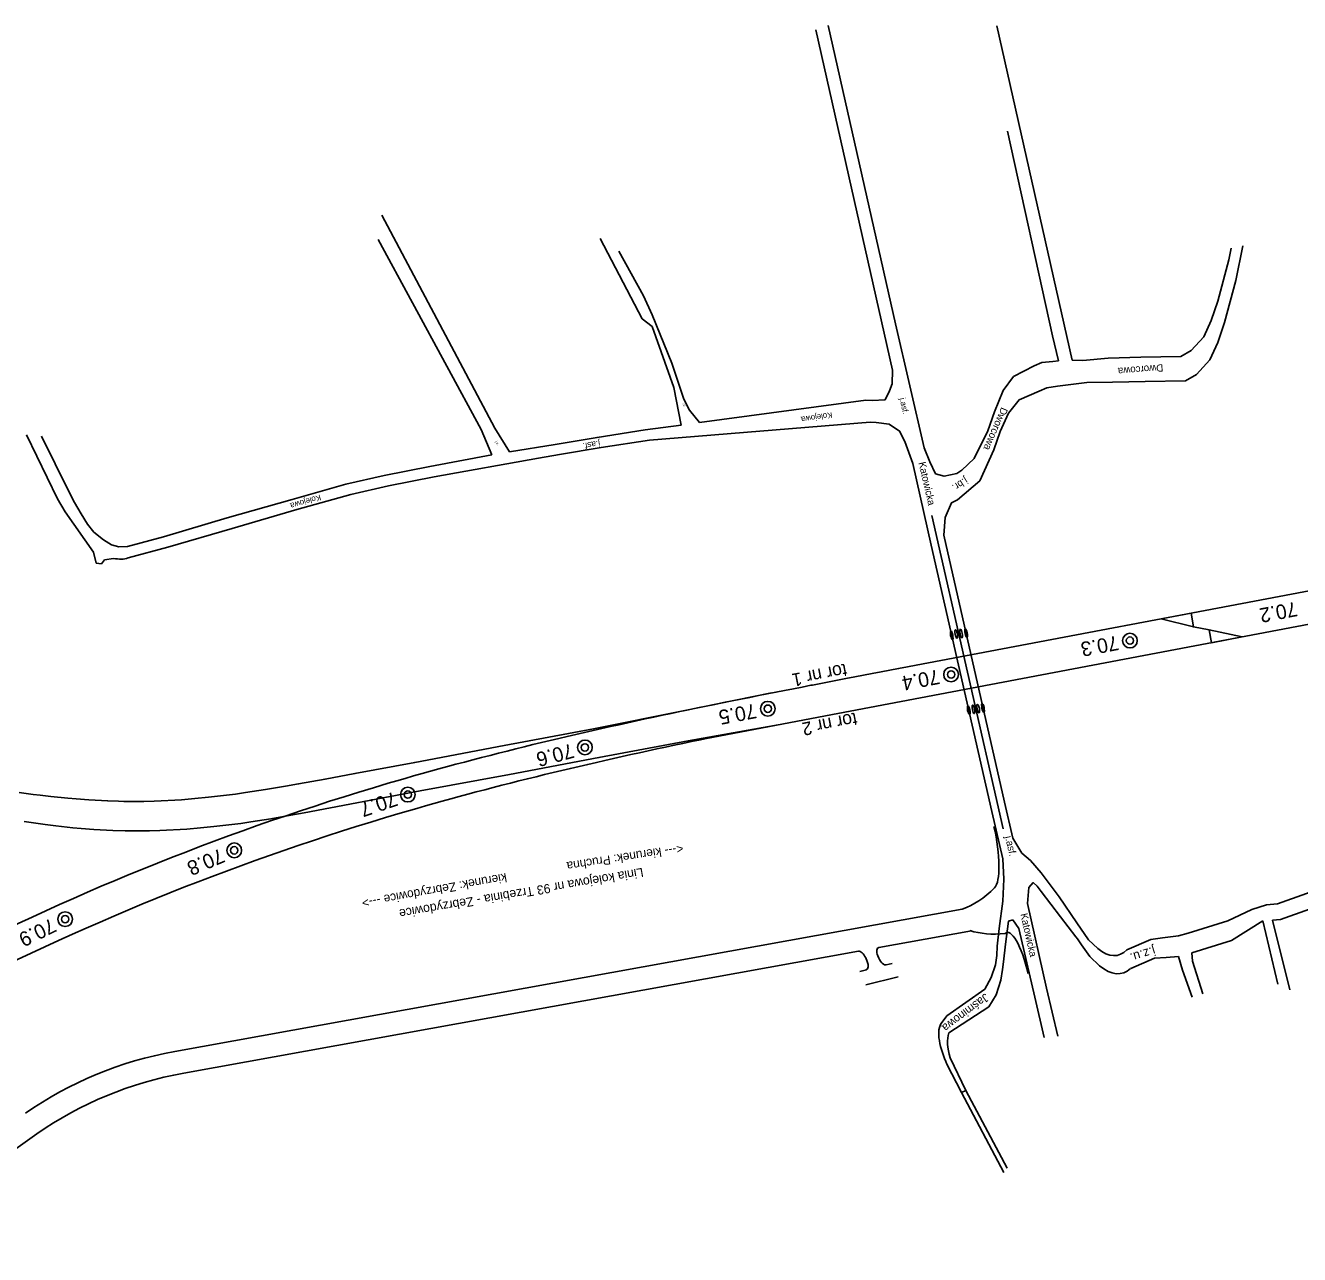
# Model space of a CAD drawing. Extents: x 6541740 to 6556805, y 5525233 to 5530361.
# Drawn here: x 6554888.2 to 6555063.1, y 5525670.1 to 5525838.8 of the extents above; entities that cross this region are included whole.
import ezdxf

# ---------------------------------------------------------------- set-up
doc = ezdxf.new("R2010")
doc.units = 0
for name, color, linetype in [('Default', 7, 'Continuous'), ('TOR_PS_OPIS_T-numeracja torow i rozjazdow', 7, 'Continuous'), ('TOR_SCH-budynki', 7, 'Continuous'), ('TOR_SCH-hektometry', 7, 'Continuous'), ('TOR_SCH-obiekty projektowane', 7, 'Continuous'), ('TOR_SCH-opisy glowne', 7, 'Continuous'), ('TOR_SCH-przejazdy+drogi istniejace', 7, 'Continuous'), ('TOR_SCH-przejazdy+drogi projektowane', 7, 'Continuous'), ('TOR_SCH-tory i rozjazdy do rozbiorki', 7, 'Continuous'), ('TOR_SCH-tory projektowane', 7, 'Continuous')]:
    doc.layers.add(name, color=color, linetype=linetype)

# ---------------------------------------------------------------- blocks, each defined once
blk = doc.blocks.new('4010_1')
at = {"layer": 'Default'}
for radius in [0.75, 0.375]:
    blk.add_circle((0, 0), radius, dxfattribs=at)

msp = doc.modelspace()

# ---------------------------------------------------------------- linework, layer by layer
at = {"layer": 'TOR_SCH-budynki'}
for centre in [(6555017.34, 5525755.36), (6555015.36, 5525755.06), (6555015.99, 5525755.25), (6555016.66, 5525755.31), (6555018.35, 5525744.91), (6555019.01, 5525745.02), (6555019.66, 5525745.11), (6555017.7, 5525744.79)]:
    msp.add_ellipse(centre, major_axis=(-0.112, 0.59), ratio=0.25, dxfattribs=at)
at = {"layer": 'TOR_SCH-obiekty projektowane'}
msp.add_line((6555012.65, 5525771.52), (6555022.43, 5525728.5), dxfattribs=at)
at = {"layer": 'TOR_SCH-przejazdy+drogi istniejace'}
for p, q in [((6554996.7, 5525838.18), (6555007.24, 5525791.47)), ((6554998.39, 5525838.77), (6555007.63, 5525797.82)), ((6555031.89, 5525792.83), (6555021.54, 5525838.72)), ((6555023.04, 5525824.27), (6555029.2, 5525796.17)), ((6554937.08, 5525812.72), (6554952.6, 5525783.49)), ((6554950.72, 5525783.34), (6554936.61, 5525809.38)), ((6554972.87, 5525798.51), (6554967.1, 5525809.53)), ((6554969.64, 5525807.78), (6554973.04, 5525801.66)), ((6554973.04, 5525801.66), (6554974.24, 5525799.08)), ((6554974.24, 5525797.45), (6554972.87, 5525798.51)), ((6554974.24, 5525799.08), (6554976.94, 5525792.43)), ((6554977.2, 5525789.1), (6554974.24, 5525797.45)), ((6555007.63, 5525797.82), (6555011.56, 5525780.78)), ((6555029.2, 5525796.17), (6555030.01, 5525792.73)), ((6554976.94, 5525792.43), (6554978.58, 5525787.48)), ((6555007.24, 5525791.47), (6555007.18, 5525789.58)), ((6554978.19, 5525783.92), (6554977.2, 5525789.1)), ((6554978.58, 5525787.48), (6554979.35, 5525785.97)), ((6554979.35, 5525785.97), (6554980.71, 5525784.26)), ((6554892.54, 5525773.8), (6554888.3, 5525782.58)), ((6554890.38, 5525782.42), (6554894.13, 5525774.8)), ((6554952.22, 5525779.82), (6554950.72, 5525783.34)), ((6554952.6, 5525783.49), (6554954.62, 5525780.24)), ((6554943.71, 5525778.23), (6554952.22, 5525779.82)), ((6554958.63, 5525779.36), (6554944.28, 5525776.84)), ((6554932.17, 5525775.8), (6554937.42, 5525777.02)), ((6554937.42, 5525777.02), (6554943.71, 5525778.23)), ((6554924.8, 5525773.73), (6554932.17, 5525775.8)), ((6554938.02, 5525775.58), (6554932.84, 5525774.41)), ((6554944.28, 5525776.84), (6554938.02, 5525775.58)), ((6554893.62, 5525772.01), (6554892.54, 5525773.8)), ((6554894.13, 5525774.8), (6554894.87, 5525773.31)), ((6554915.86, 5525771.17), (6554924.8, 5525773.73)), ((6554932.84, 5525774.41), (6554925.44, 5525772.33)), ((6554897.48, 5525766.47), (6554893.62, 5525772.01)), ((6554894.87, 5525773.31), (6554895.79, 5525771.72)), ((6554895.79, 5525771.72), (6554896.68, 5525770.33)), ((6554925.44, 5525772.33), (6554916.54, 5525769.72)), ((6554896.68, 5525770.33), (6554897.57, 5525769.23)), ((6554907.1, 5525768.57), (6554915.86, 5525771.17)), ((6554897.57, 5525769.23), (6554898.88, 5525768.16)), ((6554902.16, 5525767.28), (6554907.1, 5525768.57)), ((6554916.54, 5525769.72), (6554907.71, 5525767.15)), ((6554897.89, 5525764.95), (6554897.48, 5525766.47)), ((6554898.88, 5525768.16), (6554899.99, 5525767.48)), ((6554899.99, 5525767.48), (6554900.96, 5525767.21)), ((6554900.96, 5525767.21), (6554902.16, 5525767.28)), ((6554907.71, 5525767.15), (6554902.26, 5525765.69)), ((6554898.59, 5525764.87), (6554897.89, 5525764.95)), ((6554899.02, 5525765.43), (6554898.59, 5525764.87)), ((6554900.26, 5525765.63), (6554899.02, 5525765.43)), ((6555024.98, 5525725.17), (6555023.74, 5525727.23)), ((6555022.38, 5525724.37), (6555022.53, 5525721.57)), ((6555025.95, 5525720.43), (6555026.55, 5525721.13)), ((6555025.95, 5525720.43), (6555025.76, 5525718.25)), ((6555058.6, 5525718.09), (6555056.57, 5525717.41)), ((6555024.6, 5525714.83), (6555023.78, 5525716.02)), ((6555060.15, 5525707.17), (6555058.07, 5525715.88)), ((6555059.4, 5525715.97), (6555061.79, 5525706.4)), ((6555014.68, 5525702.81), (6555014.04, 5525701.95)), ((6555017.32, 5525692.57), (6555015.17, 5525697.06)), ((6555014.71, 5525696.19), (6555016.7, 5525692.31)), ((6555016.7, 5525692.31), (6555017.32, 5525692.57)), ((6555016.7, 5525692.31), (6555022.54, 5525681.34)), ((6555017.32, 5525692.57), (6555023, 5525681.9))]:
    msp.add_line(p, q, dxfattribs=at)
for points in [[(6555033.94, 5525789.75), (6555037.46, 5525789.81), (6555041.92, 5525789.92), (6555047.48, 5525790.02), (6555048.98, 5525790.89), (6555050.79, 5525792.86), (6555051.89, 5525795.24), (6555052.82, 5525797.99), (6555054.39, 5525803.78), (6555055.35, 5525808.53)], [(6555033.35, 5525792.77), (6555036.86, 5525793.13), (6555041.32, 5525793.24), (6555046.83, 5525793.34), (6555048.24, 5525794.16), (6555049.97, 5525796.03), (6555051, 5525798.26), (6555051.9, 5525800.92), (6555053.43, 5525806.6), (6555053.76, 5525808.21)], [(6555029.27, 5525792.66), (6555030.01, 5525792.73)], [(6555031.89, 5525792.83), (6555033.35, 5525792.77)], [(6555016.76, 5525777.72), (6555018.47, 5525779.35), (6555020.31, 5525783.15), (6555021.23, 5525785.72), (6555022.44, 5525788.69), (6555023.84, 5525790.58), (6555026.67, 5525792.05), (6555027.76, 5525792.52), (6555029.27, 5525792.66)], [(6555007.18, 5525789.58), (6555006.81, 5525788.62), (6555006.21, 5525787.37), (6555004.44, 5525787.3), (6555003.58, 5525787.33)], [(6555016.15, 5525773.67), (6555019.21, 5525776.25), (6555021.13, 5525780.53), (6555022.03, 5525783.04), (6555023.17, 5525785.57), (6555024.61, 5525787.37), (6555027.39, 5525788.6), (6555028.44, 5525789.05), (6555029.91, 5525789.25)], [(6555029.91, 5525789.25), (6555032.1, 5525789.55), (6555033.94, 5525789.75)], [(6555003.58, 5525787.33), (6554980.71, 5525784.26)], [(6555004.15, 5525784.32), (6554973.84, 5525781.86), (6554967.23, 5525780.85), (6554961.5, 5525779.87), (6554958.63, 5525779.36)], [(6555010.03, 5525778.66), (6555008.93, 5525781.68), (6555008.2, 5525783.1), (6555006.77, 5525784.05), (6555004.98, 5525784.27), (6555004.15, 5525784.32)], [(6554978.19, 5525783.92), (6554973.27, 5525783.26), (6554966.65, 5525782.24), (6554960.92, 5525781.27), (6554954.62, 5525780.24)], [(6555011.56, 5525780.78), (6555012.38, 5525778.87), (6555013.15, 5525777.24), (6555014.32, 5525776.92), (6555016.06, 5525777.28), (6555016.76, 5525777.72)], [(6555022.38, 5525724.37), (6555020.86, 5525730.87), (6555012.53, 5525767.45), (6555010.03, 5525778.66)], [(6555014.3, 5525768.83), (6555014.48, 5525771.26), (6555015.34, 5525773.27), (6555016.15, 5525773.67)], [(6555014.3, 5525768.83), (6555022.63, 5525732.15), (6555023.74, 5525727.23)], [(6555098.57, 5525731.15), (6555095, 5525730.9), (6555087.57, 5525727.52), (6555083.16, 5525725.42), (6555081.62, 5525725.24), (6555078.11, 5525724.01), (6555071.95, 5525722.81), (6555068.4, 5525721.36), (6555067.65, 5525721.06), (6555064.08, 5525719.61), (6555060.11, 5525718.2), (6555058.6, 5525718.09)], [(6555099.7, 5525728.48), (6555095.6, 5525728.43), (6555088.01, 5525725.37), (6555083.59, 5525723.27), (6555082.03, 5525723.09), (6555078.53, 5525721.86), (6555072.37, 5525720.65), (6555068.08, 5525718.91), (6555064.51, 5525717.46), (6555060.52, 5525716.05), (6555059.4, 5525715.97), (6555059.4, 5525715.97), (6555059.4, 5525715.97)], [(6555024.98, 5525725.17), (6555026.17, 5525724.17), (6555027.63, 5525722.47), (6555030.13, 5525719.15), (6555030.13, 5525719.15)], [(6555022.53, 5525721.57), (6555022.39, 5525718.58), (6555021.88, 5525714.8), (6555021.61, 5525712.39), (6555021.54, 5525711.11)], [(6555026.55, 5525721.13), (6555026.55, 5525721.13), (6555027.09, 5525720.62), (6555027.63, 5525719.9), (6555030.3, 5525716.4)], [(6555025.76, 5525718.25), (6555028.38, 5525706.65), (6555029.93, 5525700.03)], [(6555030.13, 5525719.15), (6555032.53, 5525715.61), (6555034.15, 5525713.28), (6555035.42, 5525712.06)], [(6555023.78, 5525716.02), (6555023.16, 5525715.82), (6555022.74, 5525712.65), (6555022.47, 5525710.24), (6555022.33, 5525709.21)], [(6555030.3, 5525716.4), (6555032.43, 5525713.67), (6555032.63, 5525713.41), (6555033.21, 5525712.58), (6555034.33, 5525710.98), (6555035.65, 5525709.7)], [(6555046.51, 5525713.8), (6555047.82, 5525714.2), (6555053.27, 5525715.87), (6555056.57, 5525717.41)], [(6555048.34, 5525711.48), (6555053.81, 5525713.16), (6555058.07, 5525715.88)], [(6555028.07, 5525699.88), (6555026.79, 5525705.41), (6555024.6, 5525714.83)], [(6555039.42, 5525711.9), (6555042.73, 5525713.33), (6555044.29, 5525713.53)], [(6555044.29, 5525713.53), (6555046.51, 5525713.8)], [(6555021.54, 5525711.11), (6555021.39, 5525709.83), (6555020.8, 5525708.09), (6555019.89, 5525706.48), (6555014.68, 5525702.81)], [(6555039.94, 5525709.33), (6555043.23, 5525710.76), (6555044.8, 5525710.86)], [(6555044.8, 5525710.86), (6555046.53, 5525710.97)], [(6555048.37, 5525705.39), (6555047.06, 5525709.1), (6555046.53, 5525710.97)], [(6555048.34, 5525711.48), (6555048.45, 5525710.35), (6555049.84, 5525705.84)], [(6555022.33, 5525709.21), (6555022.13, 5525707.72), (6555021.46, 5525705.73), (6555020.46, 5525704.08), (6555014.99, 5525700.49)]]:
    msp.add_lwpolyline(points, dxfattribs=at)
for centre, major_axis, ratio, start_param, end_param in [((6554897.34, 5525776.23), (-5.33, 10.37), 0.5, 2.747069, 3.066585), ((6555031.73, 5525744.58), (6.34, -33.45), 0.250307, 5.994146, 6.456591), ((6555031.51, 5525746.2), (7.11, -37.55), 0.250277, 5.994158, 6.432263), ((6555016.44, 5525698.24), (-2.05, 3.99), 0.5, 0.19715, 1.026213), ((6555018.19, 5525696.71), (-2.43, 4.74), 0.5, 0.43659, 1.248227), ((6555018.47, 5525697.33), (-3.55, 6.9), 0.5, 1.020936, 1.481176)]:
    msp.add_ellipse(centre, major_axis=major_axis, ratio=ratio, start_param=start_param, end_param=end_param, dxfattribs=at)
at = {"layer": 'TOR_SCH-przejazdy+drogi projektowane'}
for p, q in [((6555016.82, 5525717.49), (6554908.65, 5525697.93)), ((6555018.07, 5525714.52), (6555005.35, 5525712.22)), ((6555002.55, 5525711.71), (6554909.9, 5525694.96)), ((6555003.56, 5525710.79), (6555003.77, 5525710.29)), ((6555005.21, 5525711.08), (6555005.35, 5525710.75)), ((6555002.76, 5525708.94), (6555003.64, 5525709.16)), ((6555006.37, 5525709.83), (6555007.19, 5525710.03)), ((6555003.56, 5525707.11), (6555008, 5525708.18)), ((6554889.74, 5525686.63), (6554873.22, 5525675.05))]:
    msp.add_line(p, q, dxfattribs=at)
for centre, major_axis, ratio, start_param, end_param in [((6555019.62, 5525727.36), (-1.35, 7.12), 0.25, 3.312433, 4.873816), ((6554988.19, 5525861.32), (-27.33, 144.18), 0.25, 3.178225, 3.312433), ((6555090.53, 5525849.22), (74.58, 133.88), 0.25, 3.195453, 3.311202), ((6555024.31, 5525707.15), (-1.35, 7.12), 0.25, 4.873816, 6.452794), ((6555005.78, 5525711.19), (0.51, -1), 0.5, 2.99045, 4.561247), ((6555002.98, 5525710.68), (-0.51, 1), 0.5, 4.561247, 6.132043), ((6555005.92, 5525710.85), (0.51, -1), 0.5, 4.561247, 6.164201), ((6555003.19, 5525710.18), (-0.51, 1), 0.5, 3.022608, 4.561247), ((6554986.22, 5525513.69), (-92.12, 179.35), 0.5, 6.132043, 6.351843), ((6554986.22, 5525513.69), (-90.64, 176.46), 0.5, 6.132043, 6.351843)]:
    msp.add_ellipse(centre, major_axis=major_axis, ratio=ratio, start_param=start_param, end_param=end_param, dxfattribs=at)
at = {"layer": 'TOR_SCH-tory i rozjazdy do rozbiorki'}
for points in [[(6555044.13, 5525757.34), (6555048.26, 5525758.12), (6555048.55, 5525756.22)], [(6555055.23, 5525754.85), (6555051.03, 5525754.05), (6555050.73, 5525755.8)]]:
    msp.add_lwpolyline(points, close=True, dxfattribs=at)
for points in [[(6555050.73, 5525755.8), (6555048.55, 5525756.22)], [(6554990.62, 5525747.15), (6554990.62, 5525747.15), (6554978.5, 5525744.69), (6554978.5, 5525744.69), (6554966.17, 5525742.23), (6554966.17, 5525742.23), (6554953.9, 5525739.93), (6554953.9, 5525739.93), (6554941.61, 5525737.63), (6554941.61, 5525737.63), (6554933.41, 5525736.08), (6554929.31, 5525735.32), (6554929.31, 5525735.32), (6554925.67, 5525734.66), (6554923.85, 5525734.34), (6554921.11, 5525733.89), (6554918.37, 5525733.47), (6554916.99, 5525733.28), (6554916.99, 5525733.28), (6554915.35, 5525733.06), (6554914.53, 5525732.97), (6554913.3, 5525732.83), (6554911.44, 5525732.65), (6554909.58, 5525732.5), (6554908.65, 5525732.43), (6554906.78, 5525732.34), (6554905.84, 5525732.3), (6554904.43, 5525732.27), (6554904.43, 5525732.27), (6554902.78, 5525732.26), (6554901.68, 5525732.27), (6554900.95, 5525732.29), (6554899.47, 5525732.34), (6554899.47, 5525732.34), (6554898.6, 5525732.37), (6554896.87, 5525732.48), (6554895.12, 5525732.61), (6554893.96, 5525732.71), (6554891.63, 5525732.94), (6554891.62, 5525732.94), (6554890.19, 5525733.11), (6554889.23, 5525733.23), (6554887.3, 5525733.49)], [(6554991.55, 5525742.77), (6554979.19, 5525740.59), (6554966.92, 5525738.28), (6554966.92, 5525738.28), (6554954.65, 5525735.97), (6554954.65, 5525735.97), (6554942.36, 5525733.7), (6554942.36, 5525733.7), (6554938.26, 5525732.93), (6554930.05, 5525731.38), (6554930.05, 5525731.38), (6554926.42, 5525730.7), (6554924.59, 5525730.37), (6554921.86, 5525729.89), (6554920.03, 5525729.59), (6554919.11, 5525729.45), (6554917.74, 5525729.25), (6554917.74, 5525729.25), (6554916.1, 5525729.04), (6554915.28, 5525728.94), (6554914.05, 5525728.8), (6554912.19, 5525728.62), (6554910.33, 5525728.46), (6554909.4, 5525728.4), (6554907.53, 5525728.3), (6554906.6, 5525728.26), (6554905.19, 5525728.22), (6554905.19, 5525728.22), (6554903.71, 5525728.21), (6554902.97, 5525728.21), (6554901.86, 5525728.22), (6554900.18, 5525728.27), (6554900.18, 5525728.27), (6554899.31, 5525728.31), (6554897.57, 5525728.41), (6554895.83, 5525728.54), (6554894.66, 5525728.65), (6554893.88, 5525728.73), (6554892.33, 5525728.91), (6554892.32, 5525728.91), (6554890.88, 5525729.09), (6554889.91, 5525729.22), (6554887.98, 5525729.5)]]:
    msp.add_lwpolyline(points, dxfattribs=at)
at = {"layer": 'TOR_SCH-tory projektowane'}
for p, q in [((6555221.45, 5525790.95), (6555010.48, 5525750.96)), ((6555222.13, 5525786.49), (6554997.05, 5525743.82)), ((6554997.05, 5525743.82), (6554981.45, 5525740.86))]:
    msp.add_line(p, q, dxfattribs=at)
for points in [[(6555010.48, 5525750.96), (6555009.27, 5525750.73), (6555008.07, 5525750.5), (6555006.86, 5525750.27), (6555005.66, 5525750.04), (6555004.45, 5525749.82), (6555003.25, 5525749.59), (6555002.05, 5525749.36), (6555000.84, 5525749.13), (6554996.23, 5525748.24)], [(6554996.23, 5525748.24), (6554996.03, 5525748.2), (6554994.83, 5525747.97), (6554993.62, 5525747.73), (6554992.42, 5525747.5), (6554991.22, 5525747.26), (6554990.02, 5525747.03), (6554988.82, 5525746.79), (6554987.62, 5525746.55), (6554986.42, 5525746.31), (6554985.22, 5525746.07), (6554984.02, 5525745.83), (6554982.82, 5525745.58), (6554981.63, 5525745.34), (6554980.43, 5525745.09), (6554979.23, 5525744.85), (6554978.04, 5525744.6), (6554976.84, 5525744.34), (6554975.65, 5525744.09), (6554974.46, 5525743.84), (6554973.26, 5525743.58), (6554972.07, 5525743.32), (6554970.88, 5525743.06), (6554969.69, 5525742.8), (6554968.5, 5525742.54), (6554967.31, 5525742.27), (6554966.13, 5525742), (6554964.94, 5525741.73), (6554963.75, 5525741.46), (6554962.57, 5525741.18), (6554961.39, 5525740.9), (6554960.2, 5525740.62), (6554959.02, 5525740.34), (6554957.84, 5525740.06), (6554956.66, 5525739.77), (6554955.49, 5525739.48), (6554954.31, 5525739.18), (6554953.14, 5525738.89), (6554951.96, 5525738.59), (6554950.79, 5525738.29), (6554949.62, 5525737.98), (6554948.45, 5525737.67), (6554947.28, 5525737.36), (6554946.11, 5525737.05), (6554944.95, 5525736.73), (6554943.78, 5525736.41), (6554942.62, 5525736.09), (6554941.46, 5525735.76), (6554940.3, 5525735.43), (6554939.14, 5525735.09), (6554937.99, 5525734.75)], [(6554981.45, 5525740.86), (6554980.85, 5525740.74), (6554979.65, 5525740.49), (6554978.46, 5525740.23), (6554977.27, 5525739.98), (6554976.07, 5525739.73), (6554974.88, 5525739.47), (6554973.69, 5525739.21), (6554972.5, 5525738.95), (6554971.31, 5525738.69), (6554970.12, 5525738.43), (6554968.93, 5525738.16), (6554967.74, 5525737.89), (6554966.56, 5525737.62), (6554965.37, 5525737.35), (6554964.19, 5525737.07), (6554963, 5525736.79), (6554961.82, 5525736.51), (6554960.64, 5525736.23), (6554959.46, 5525735.95), (6554958.28, 5525735.66), (6554957.1, 5525735.37), (6554955.93, 5525735.07), (6554954.75, 5525734.78), (6554953.58, 5525734.48), (6554952.41, 5525734.18), (6554951.24, 5525733.87), (6554950.07, 5525733.56), (6554948.9, 5525733.25), (6554947.73, 5525732.94), (6554946.57, 5525732.62), (6554945.4, 5525732.3), (6554944.24, 5525731.97), (6554943.08, 5525731.64), (6554941.92, 5525731.31), (6554940.76, 5525730.98), (6554939.6, 5525730.64)]]:
    msp.add_lwpolyline(points, dxfattribs=at)
for centre, major_axis, start_param, end_param in [((6555516.78, 5524462.45), (-640.8, 1247.55), 6.188263, 6.378108), ((6555517.43, 5524460.63), (-639.66, 1245.32), 6.188355, 6.378016)]:
    msp.add_ellipse(centre, major_axis=major_axis, ratio=0.5, start_param=start_param, end_param=end_param, dxfattribs=at)

# ---------------------------------------------------------------- block references
at = {"layer": 'TOR_SCH-hektometry', "xscale": 1.345963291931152, "yscale": 1.345963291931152}
for p in [(6555039.84, 5525754.34), (6555015.28, 5525749.69), (6554990.11, 5525744.99)]:
    msp.add_blockref('4010_1', p, dxfattribs=at)
at = {"layer": 'TOR_SCH-hektometry'}
for p, xscale, yscale, rotation in [((6554964.99, 5525739.68), 1.345963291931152, 1.3459632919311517, 4.247698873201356), ((6554940.67, 5525733.2), 1.345963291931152, 1.3459632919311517, 4.247698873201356), ((6554916.83, 5525725.55), 1.345963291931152, 1.3459632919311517, 4.247698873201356), ((6554893.61, 5525716.1), 1.3459632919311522, 1.3459632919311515, 7.546628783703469)]:
    msp.add_blockref('4010_1', p, dxfattribs=dict(at, xscale=xscale, yscale=yscale, rotation=rotation))

# ---------------------------------------------------------------- texts
at = {"layer": 'TOR_PS_OPIS_T-numeracja torow i rozjazdow'}
for s, rotation, p in [('tor nr 1', 191.0237, (6555000.79, 5525751.21)), ('tor nr 2', 191.0133, (6555002.18, 5525744.49))]:
    msp.add_text(s, height=1.8, rotation=rotation, dxfattribs=at).set_placement(p)
at = {"layer": 'TOR_SCH-hektometry'}
for s, rotation, p in [('70.2', 190.7691, (6555062.62, 5525759.7)), ('70.3', 190.7691, (6555038.07, 5525755.05)), ('70.4', 190.7691, (6555013.5, 5525750.39)), ('70.5', 190.7691, (6554988.34, 5525745.7)), ('70.6', 195.0168, (6554963.17, 5525740.25)), ('70.7', 198.8052, (6554938.82, 5525733.65)), ('70.8', 202.8689, (6554914.95, 5525725.87)), ('70.9', 206.1678, (6554891.71, 5525716.31))]:
    msp.add_text(s, height=2, rotation=rotation, dxfattribs=at).set_placement(p)
at = {"layer": 'TOR_SCH-opisy glowne'}
for s, height, rotation, p in [('<--- kierunek: Pruchna', 1.2202, 188.7861, (6554978.41, 5525726.41)), ('Linia kolejowa nr 93 Trzebinia - Zebrzydowice', 1.2535, 189.7097, (6554972.91, 5525723.16)), ('kierunek: Zebrzydowice --->', 1.2202, 190.2881, (6554954.14, 5525722.45))]:
    msp.add_text(s, height=height, rotation=rotation, dxfattribs=at).set_placement(p)
at = {"layer": 'TOR_SCH-przejazdy+drogi istniejace'}
for s, height, rotation, p in [('Dworcowa', 1, 184.7563, (6555044.37, 5525792.29)), ('j.asf.', 0.8, 282.9017, (6555008.19, 5525787.58)), ('j.z.', 0.314, 296.4445, (6554978.39, 5525786.87)), ('Kolejowa', 0.8, 188.6691, (6554998.91, 5525785.71)), ('Dworcowa', 1, 246.4462, (6555022.2, 5525786.45)), ('j.z.', 0.34, 300.4088, (6554952.65, 5525781.64)), ('j.asf.', 0.848, 189.2587, (6554967.01, 5525781.82)), ('Katowicka', 1, 282.9297, (6555010.8, 5525778.76)), ('j.br.', 1, 212.2378, (6555017.2, 5525776.81)), ('Kolejowa', 0.8, 196.2308, (6554928.61, 5525774.39)), ('j.asf.', 1, 282.9017, (6555022.68, 5525727.42)), ('Katowicka', 1, 282.7884, (6555024.78, 5525716.79)), ('j.z.u.', 1.25, 197.0568, (6555043.12, 5525712.37)), ('Jaśminowa', 1.132, 216.9369, (6555019.96, 5525705.98))]:
    msp.add_text(s, height=height, rotation=rotation, dxfattribs=at).set_placement(p)

doc.saveas('drawing.dxf')
